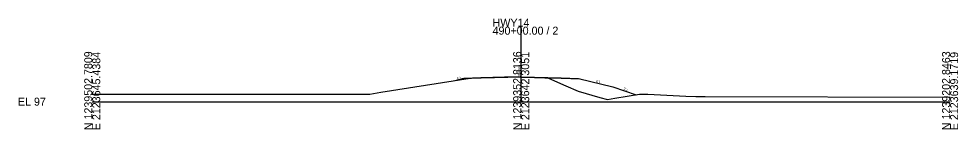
# Model space of a CAD drawing. Extents: x -26 to 303, y -10 to 11521.
# Drawn here: x -25.7 to 302.8, y 1490.3 to 1529.1 of the extents above; entities that cross this region are included whole.
import ezdxf

# ---------------------------------------------------------------- set-up
doc = ezdxf.new("R2010")
doc.units = 0
for name, color, linetype in [('XS_CELL', 7, 'Continuous'), ('XS_P_FINISHED_GRADE', 7, 'Continuous'), ('XS_P_SUBGRADE_GRANULAR', 7, 'Continuous'), ('XS_P_SUBGRADE_LEVELING', 7, 'Continuous'), ('XS_P_TX_FS_BS', 7, 'Continuous'), ('XS_X_GROUND', 7, 'Continuous'), ('XS_X_GROUND_TX', 7, 'Continuous')]:
    doc.layers.add(name, color=color, linetype=linetype)

msp = doc.modelspace()

# ---------------------------------------------------------------- linework, layer by layer
at = {"layer": 'XS_CELL'}
for p, q in [((150, 1500), (150, 1526.34)), ((0, 1500), (150, 1500)), ((150, 1500), (300, 1500))]:
    msp.add_line(p, q, dxfattribs=at)
at = {"layer": 'XS_P_FINISHED_GRADE'}
for p, q in [((130, 1508.17), (126.79, 1507.37)), ((136, 1508.41), (130, 1508.17)), ((150, 1508.69), (136, 1508.41)), ((150, 1508.69), (164, 1508.41)), ((164, 1508.41), (170, 1508.17)), ((170, 1508.17), (182, 1505.17)), ((182, 1505.17), (190.23, 1502.43))]:
    msp.add_line(p, q, dxfattribs=at)
at = {"layer": 'XS_P_SUBGRADE_GRANULAR'}
for p, q in [((136, 1508.28), (129.4, 1508.02)), ((164, 1508.28), (170.6, 1508.02))]:
    msp.add_line(p, q, dxfattribs=at)
at = {"layer": 'XS_P_SUBGRADE_LEVELING'}
for p, q in [((150, 1508.56), (136, 1508.28)), ((136, 1508.28), (136, 1508.41)), ((150, 1508.56), (164, 1508.28)), ((164, 1508.28), (164, 1508.41))]:
    msp.add_line(p, q, dxfattribs=at)
at = {"layer": 'XS_X_GROUND'}
for p, q in [((100.94, 1503.31), (132.21, 1508.22)), ((132.21, 1508.22), (135.85, 1508.48)), ((135.85, 1508.48), (144.12, 1508.71)), ((144.12, 1508.71), (146.63, 1508.78)), ((146.63, 1508.78), (150, 1508.69)), ((150, 1508.69), (157.41, 1508.46)), ((157.41, 1508.46), (158.28, 1508.37)), ((158.28, 1508.37), (159.55, 1508.23)), ((159.55, 1508.23), (165.67, 1505.52)), ((165.67, 1505.52), (169.97, 1503.64)), ((0, 1502.66), (6.59, 1502.67)), ((6.59, 1502.67), (14.65, 1502.69)), ((14.65, 1502.69), (57.78, 1502.7)), ((57.78, 1502.7), (97.03, 1502.69)), ((97.03, 1502.69), (100.94, 1503.31)), ((169.97, 1503.64), (177.56, 1501.48)), ((177.56, 1501.48), (180.23, 1500.75)), ((182.79, 1501.23), (191.33, 1502.6)), ((191.33, 1502.6), (194.26, 1502.66)), ((194.26, 1502.66), (207.6, 1501.9)), ((207.6, 1501.9), (211.12, 1501.77)), ((211.12, 1501.77), (214.31, 1501.77)), ((214.31, 1501.77), (300, 1501.53)), ((180.23, 1500.75), (182.79, 1501.23))]:
    msp.add_line(p, q, dxfattribs=at)

# ---------------------------------------------------------------- texts
at = {"layer": 'XS_CELL'}
for s, p in [('HWY14', (140, 1526.34)), ('490+00.00 / 2', (140, 1523.54)), ('EL 97', (-26, 1498.6))]:
    msp.add_text(s, height=2.8, dxfattribs=at).set_placement(p)
for s, p in [('N 1239502.7809', (0, 1490)), ('E 2123645.4384', (2.8, 1490)), ('N 1239352.8136', (150, 1490)), ('E 2123642.3051', (152.8, 1490)), ('N 1239202.8463', (300, 1490)), ('E 2123639.1719', (302.8, 1490))]:
    msp.add_text(s, height=2.8, rotation=90, dxfattribs=at).set_placement(p)
at = {"layer": 'XS_P_TX_FS_BS'}
for s, rotation, p in [('4:1', 14.0362, (127.57, 1507.71)), ('4:1', 345.9638, (176.07, 1506.92)), ('3:1', 341.5651, (185.72, 1504.25))]:
    msp.add_text(s, height=0.8, rotation=rotation, dxfattribs=at).set_placement(p)
at = {"layer": 'XS_X_GROUND_TX'}
msp.add_text('105.69', height=1, rotation=90, dxfattribs=at).set_placement((150, 1508.79))

doc.saveas('drawing.dxf')
